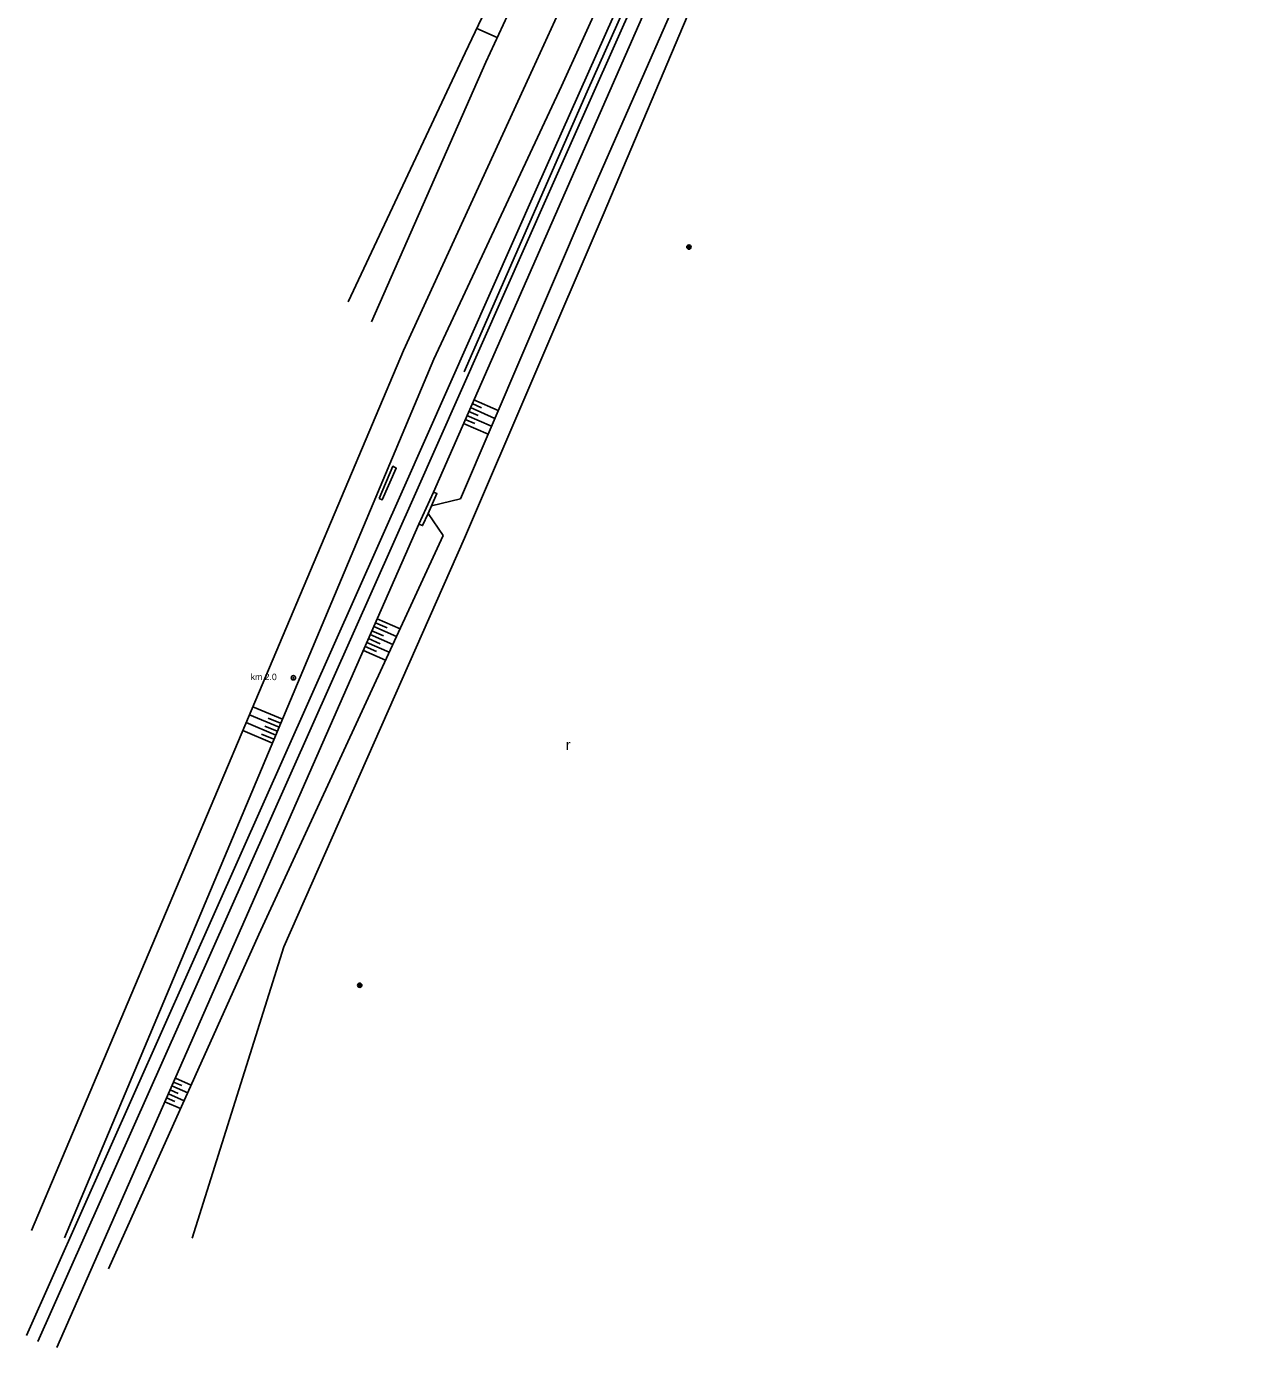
# Model space of a CAD drawing. Extents: x -539694 to -539148, y -1156467 to -1155920.
# Drawn here: x -539348.4 to -539207.8, y -1156425.2 to -1156272.3 of the extents above; entities that cross this region are included whole.
import ezdxf

# ---------------------------------------------------------------- set-up
doc = ezdxf.new("R2010")
doc.units = 0
for name, color, linetype in [('Vrstva 11', 7, 'Continuous'), ('Vrstva 12', 7, 'Continuous'), ('Vrstva 13', 7, 'Continuous'), ('Vrstva 14', 7, 'Continuous'), ('Vrstva 15', 7, 'Continuous'), ('Vrstva 23', 7, 'Continuous'), ('Vrstva 25', 7, 'Continuous'), ('Vrstva 36', 7, 'Continuous'), ('Vrstva 41', 7, 'Continuous')]:
    doc.layers.add(name, color=color, linetype=linetype)

msp = doc.modelspace()

# ---------------------------------------------------------------- linework, layer by layer
at = {"layer": 'Vrstva 11'}
for p, q in [((-539301.35, -1156326.15), (-539303.02, -1156329.84)), ((-539301.96, -1156328.62), (-539301.58, -1156327.75))]:
    msp.add_line(p, q, dxfattribs=at)
for points in [[(-539307.62, -1156326.87), (-539306.02, -1156323.16), (-539305.64, -1156323.36), (-539307.28, -1156327.05), (-539307.62, -1156326.87)], [(-539301.58, -1156327.75), (-539300.94, -1156326.32), (-539301.35, -1156326.15)], [(-539303.02, -1156329.84), (-539302.6, -1156330.03), (-539301.96, -1156328.62)]]:
    msp.add_lwpolyline(points, dxfattribs=at)
at = {"layer": 'Vrstva 12'}
for p, q in [((-539268.71, -1156244.59), (-539289.44, -1156291.13)), ((-539288.07, -1156291.72), (-539267.32, -1156245.04)), ((-539289.44, -1156291.13), (-539304.79, -1156325.72)), ((-539303.43, -1156326.32), (-539288.07, -1156291.72)), ((-539304.79, -1156325.72), (-539326.58, -1156374.62)), ((-539325.2, -1156375.26), (-539303.43, -1156326.32)), ((-539326.58, -1156374.62), (-539348.45, -1156423.75)), ((-539347.11, -1156424.44), (-539325.2, -1156375.26))]:
    msp.add_line(p, q, dxfattribs=at)
for radius in [0.25, 0.03]:
    msp.add_circle((-539317.55, -1156347.64), radius, dxfattribs=at)
at = {"layer": 'Vrstva 13'}
for p, q in [((-539283.54, -1156279.77), (-539267.5, -1156243.82)), ((-539297.79, -1156312.22), (-539283.54, -1156279.77))]:
    msp.add_line(p, q, dxfattribs=at)
at = {"layer": 'Vrstva 14'}
for p, q in [((-539280.5, -1156238.83), (-539297.65, -1156275.3)), ((-539295.28, -1156276.38), (-539278.45, -1156239.99)), ((-539289.82, -1156277.16), (-539273.36, -1156240.91)), ((-539269.91, -1156242.48), (-539286.5, -1156279.16)), ((-539268.91, -1156259.37), (-539283.78, -1156293.21)), ((-539297.65, -1156275.3), (-539311.22, -1156304.13)), ((-539308.52, -1156306.44), (-539295.28, -1156276.38)), ((-539304.81, -1156309.77), (-539289.82, -1156277.16)), ((-539286.5, -1156279.16), (-539301.3, -1156310.76)), ((-539283.78, -1156293.21), (-539298.21, -1156326.91)), ((-539347.87, -1156411.59), (-539304.81, -1156309.77)), ((-539301.3, -1156310.76), (-539344.06, -1156412.44)), ((-539298.21, -1156326.91), (-539301.58, -1156327.75)), ((-539301.96, -1156328.62), (-539300.22, -1156331.16)), ((-539303.02, -1156329.84), (-539344.93, -1156425.15)), ((-539300.22, -1156331.16), (-539321.54, -1156377.34)), ((-539321.54, -1156377.34), (-539338.94, -1156416.05))]:
    msp.add_line(p, q, dxfattribs=at)
msp.add_lwpolyline([(-539301.35, -1156326.15), (-539226.818, -1156156.579), (-539226.336, -1156155.482), (-539207.8, -1156113.31)], dxfattribs=at)
at = {"layer": 'Vrstva 15'}
for p, q in [((-539296.33, -1156272.494), (-539293.968, -1156273.544)), ((-539297.052, -1156316.372), (-539294.229, -1156317.613)), ((-539296.847, -1156315.905), (-539295.762, -1156316.382)), ((-539296.65, -1156315.457), (-539293.836, -1156316.694)), ((-539297.652, -1156317.736), (-539296.567, -1156318.213)), ((-539297.455, -1156317.288), (-539294.623, -1156318.533)), ((-539297.249, -1156316.821), (-539296.165, -1156317.297)), ((-539297.857, -1156318.203), (-539295.017, -1156319.452)), ((-539307.841, -1156340.804), (-539305.207, -1156341.962)), ((-539308.451, -1156342.191), (-539307.111, -1156342.78)), ((-539308.244, -1156341.719), (-539305.626, -1156342.87)), ((-539308.048, -1156341.276), (-539306.708, -1156341.865)), ((-539309.256, -1156344.022), (-539307.916, -1156344.611)), ((-539309.049, -1156343.55), (-539306.465, -1156344.686)), ((-539308.854, -1156343.106), (-539307.513, -1156343.696)), ((-539308.646, -1156342.635), (-539306.046, -1156343.778)), ((-539309.451, -1156344.466), (-539306.884, -1156345.594)), ((-539318.821, -1156352.425), (-539322.241, -1156350.987)), ((-539319.597, -1156354.268), (-539323.02, -1156352.829)), ((-539319.209, -1156353.347), (-539322.63, -1156351.908)), ((-539319.41, -1156353.824), (-539320.842, -1156353.221)), ((-539319.022, -1156352.902), (-539320.454, -1156352.3)), ((-539319.984, -1156355.19), (-539323.409, -1156353.75)), ((-539319.797, -1156354.745), (-539321.23, -1156354.143)), ((-539331.417, -1156394.418), (-539330.475, -1156394.832)), ((-539331.212, -1156393.954), (-539329.372, -1156394.763)), ((-539332.017, -1156395.785), (-539330.192, -1156396.588)), ((-539331.819, -1156395.334), (-539330.877, -1156395.748)), ((-539331.615, -1156394.869), (-539329.782, -1156395.675)), ((-539332.42, -1156396.7), (-539330.602, -1156397.5)), ((-539332.222, -1156396.249), (-539331.28, -1156396.663))]:
    msp.add_line(p, q, dxfattribs=at)
at = {"layer": 'Vrstva 23'}
for p, q in [((-539267.32, -1156260.16), (-539281.71, -1156294.05)), ((-539281.71, -1156294.05), (-539297.73, -1156331.49)), ((-539297.73, -1156331.49), (-539318.67, -1156378.77)), ((-539318.67, -1156378.77), (-539329.28, -1156412.5))]:
    msp.add_line(p, q, dxfattribs=at)
at = {"layer": 'Vrstva 25'}
for centre, radius in [((-539271.77, -1156297.79), 0.25), ((-539271.77, -1156297.79), 0.2), ((-539271.77, -1156297.79), 0.15), ((-539271.77, -1156297.79), 0.1), ((-539271.77, -1156297.79), 0.05), ((-539309.87, -1156383.22), 0.25), ((-539309.87, -1156383.22), 0.2), ((-539309.87, -1156383.22), 0.15), ((-539309.87, -1156383.22), 0.1), ((-539309.87, -1156383.22), 0.05)]:
    msp.add_circle(centre, radius, dxfattribs=at)

# ---------------------------------------------------------------- texts
at = {"layer": 'Vrstva 36'}
msp.add_text('r', height=1.2, dxfattribs=at).set_placement((-539286.015, -1156355.997))
at = {"layer": 'Vrstva 41'}
msp.add_text('km 2.0', height=0.75, dxfattribs=at).set_placement((-539322.487, -1156347.909))

doc.saveas('drawing.dxf')
